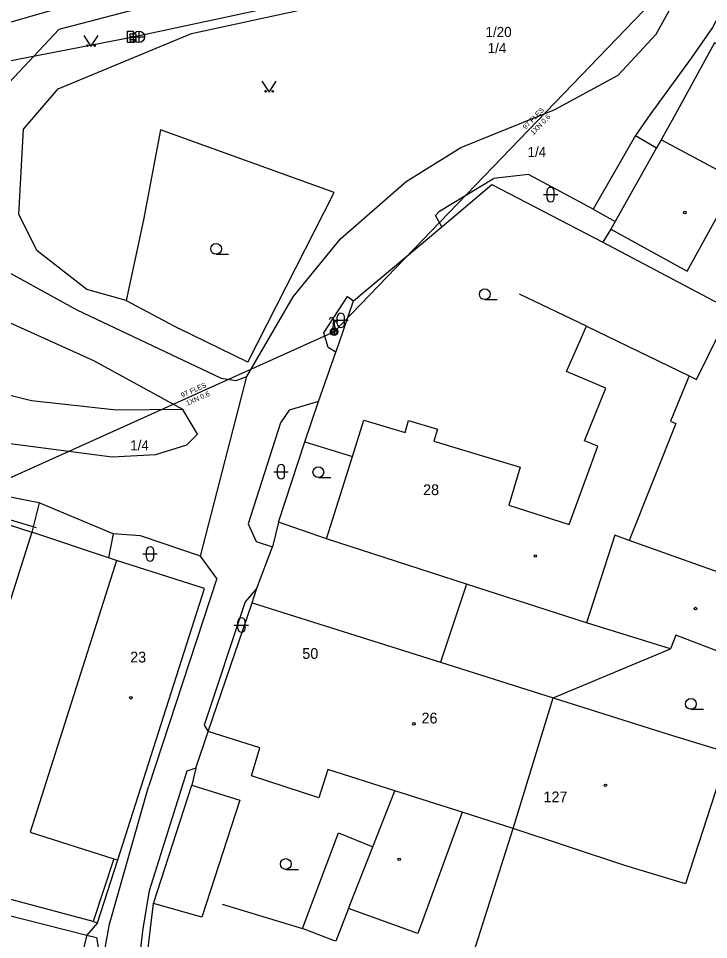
# Model space of a CAD drawing. Extents: x -836739 to -834468, y -1071001 to -1070126.
# Drawn here: x -836549.1 to -836501, y -1070395 to -1070330.7 of the extents above; entities that cross this region are included whole.
import ezdxf

# ---------------------------------------------------------------- set-up
doc = ezdxf.new("R2010")
doc.units = 0
for name, color, linetype in [('f001_pol_linie', 7, 'Continuous'), ('f001_pol_texty', 7, 'Continuous'), ('f001_pol_znacky', 7, 'Continuous'), ('f002_inz_linie_mimo_CETIN', 7, 'Continuous'), ('f005_nadz_ved_linie', 7, 'Continuous'), ('f005_nadz_ved_texty', 7, 'Continuous'), ('f005_nadz_ved_znacky', 7, 'Continuous'), ('f307_kabel_metal', 7, 'Continuous'), ('f307_kabel_metal_ann', 7, 'Continuous'), ('f309_trubka', 7, 'Continuous'), ('f373_podpera', 7, 'Continuous')]:
    doc.layers.add(name, color=color, linetype=linetype)

msp = doc.modelspace()

# ---------------------------------------------------------------- linework, layer by layer
at = {"layer": 'f001_pol_linie'}
for points in [[(-836536.4, -1070368.21), (-836533.17, -1070355.68), (-836529.95, -1070350.14), (-836526.64, -1070346.09), (-836522.06, -1070342.08), (-836518.27, -1070339.72), (-836511.7, -1070337.08), (-836507.28, -1070334.68), (-836504.64, -1070331.81), (-836503.25, -1070329.28), (-836502.09, -1070325.77), (-836501.89, -1070323.62), (-836502.72, -1070321.42), (-836505.15, -1070318.12), (-836506.77, -1070316.06), (-836508.98, -1070315.34)], [(-836541.58, -1070350.39), (-836544.34, -1070349.63), (-836547.79, -1070346.93), (-836549.07, -1070344.38), (-836548.75, -1070338.43), (-836546.32, -1070335.63), (-836537.04, -1070331.76), (-836528.76, -1070329.97), (-836518.57, -1070326.72), (-836515.72, -1070324.62), (-836506.05, -1070328.35), (-836503.77, -1070324.55), (-836503.82, -1070321.79), (-836505.15, -1070318.12)], [(-836503.77, -1070324.55), (-836515, -1070322.63), (-836520.35, -1070325.26), (-836523.26, -1070325.47), (-836531.42, -1070327.59), (-836546.27, -1070331.48), (-836550.47, -1070335.93), (-836551.89, -1070339.77), (-836552.03, -1070343.83), (-836551.31, -1070347.61)], [(-836456.49, -1070361.78), (-836456.25, -1070359.46), (-836459.92, -1070355.96), (-836465.33, -1070351.01), (-836472.65, -1070344.35), (-836480.74, -1070337.07), (-836490.99, -1070328.59), (-836496.17, -1070324.43), (-836496.72, -1070324.41), (-836497.13, -1070324.67), (-836498.53, -1070327.13), (-836499.22, -1070328.53), (-836500.71, -1070331.34), (-836502.21, -1070333.5), (-836505.09, -1070337.45), (-836506.09, -1070338.88), (-836509.04, -1070344.01), (-836513.54, -1070341.59), (-836515.98, -1070341.87)], [(-836561.92, -1070332.6), (-836562.29, -1070333.46), (-836559.69, -1070338.29), (-836553.98, -1070345.27), (-836551.31, -1070347.61), (-836545.02, -1070351.03), (-836534.96, -1070355.81), (-836533.92, -1070355.97), (-836533.17, -1070355.68)], [(-836493.1, -1070336.59), (-836496.65, -1070334.47), (-836500.57, -1070332.42), (-836503.41, -1070337.61)], [(-836615.19, -1070379.26), (-836605.62, -1070372.23), (-836598.73, -1070367.69), (-836589.69, -1070363.97), (-836577.99, -1070361.29), (-836567.54, -1070359.78), (-836561.76, -1070359.47), (-836555.57, -1070359.6), (-836542.56, -1070361.3), (-836539.53, -1070361.13), (-836537.36, -1070360.46), (-836536.61, -1070359.71), (-836537.63, -1070358), (-836543.83, -1070354.6), (-836550.65, -1070351.53), (-836553.41, -1070349.94), (-836556.85, -1070346.77), (-836557.71, -1070345.9), (-836560.14, -1070342.4), (-836564.87, -1070335.97), (-836569.41, -1070333.94)], [(-836502.34, -1070355.64), (-836501.82, -1070355.9), (-836499.44, -1070351.03), (-836494.05, -1070339.35), (-836493.01, -1070337.1)], [(-836503.41, -1070337.61), (-836504.3, -1070339.18)], [(-836533.11, -1070354.69), (-836527.08, -1070342.86), (-836539.2, -1070338.48), (-836540.39, -1070344.76), (-836541.58, -1070350.39), (-836537.92, -1070352.34)], [(-836506.09, -1070338.88), (-836504.62, -1070339.74)], [(-836504.3, -1070339.18), (-836504.62, -1070339.74), (-836507.5, -1070344.87), (-836507.81, -1070345.41)], [(-836502.49, -1070348.34), (-836498.99, -1070342.03), (-836504.3, -1070339.18)], [(-836519.59, -1070345.25), (-836520.02, -1070344.47), (-836519.75, -1070344.15), (-836515.98, -1070341.87)], [(-836525.73, -1070350.4), (-836519.59, -1070345.25), (-836516.09, -1070342.31), (-836508.36, -1070346.32)], [(-836509.04, -1070344.01), (-836507.5, -1070344.87)], [(-836507.81, -1070345.41), (-836508.36, -1070346.32)], [(-836507.81, -1070345.41), (-836502.49, -1070348.34)], [(-836508.36, -1070346.32), (-836499.44, -1070351.03)], [(-836509.51, -1070352.17), (-836514.16, -1070349.95)], [(-836526.98, -1070354), (-836527.51, -1070353.66), (-836527.82, -1070352.64), (-836526.76, -1070351.04), (-836526.15, -1070350.11), (-836525.73, -1070350.4)], [(-836526.79, -1070353.47), (-836525.73, -1070350.4)], [(-836533.11, -1070354.69), (-836537.92, -1070352.34)], [(-836506.52, -1070367.12), (-836507.53, -1070366.76), (-836509.49, -1070372.86), (-836517.87, -1070370.16), (-836527.63, -1070367.01), (-836525.81, -1070361.26), (-836525.01, -1070358.74), (-836522.15, -1070359.6), (-836521.9, -1070358.76), (-836519.88, -1070359.35), (-836520.14, -1070360.2), (-836514.12, -1070362.01), (-836514.92, -1070364.66), (-836510.71, -1070366), (-836508.7, -1070360.55), (-836509.64, -1070360.18), (-836508.16, -1070356.49), (-836510.89, -1070355.34), (-836509.51, -1070352.17), (-836502.34, -1070355.64), (-836503.65, -1070358.81), (-836503.28, -1070358.96), (-836506.52, -1070367.12)], [(-836528.18, -1070357.44), (-836526.98, -1070354), (-836526.79, -1070353.47)], [(-836537.63, -1070358), (-836542.27, -1070358.03), (-836548.18, -1070357.38), (-836559.01, -1070354.67), (-836562.23, -1070356.44)], [(-836528.18, -1070357.44), (-836530.22, -1070358.03), (-836530.82, -1070358.93), (-836533.08, -1070365.97), (-836532.53, -1070367.2), (-836531.39, -1070367.56)], [(-836530.96, -1070365.85), (-836529.13, -1070360.25), (-836528.18, -1070357.44)], [(-836529.13, -1070360.25), (-836525.81, -1070361.26)], [(-836547.65, -1070364.49), (-836556.3, -1070362.82), (-836560.36, -1070362.88), (-836566.97, -1070363.32), (-836574.87, -1070363.96), (-836583.1, -1070365.51), (-836589.57, -1070367.22), (-836595.04, -1070369.19), (-836598.97, -1070371.82)], [(-836548.17, -1070366.54), (-836554, -1070384.9), (-836561.97, -1070382.37), (-836556.16, -1070364.42), (-836556.02, -1070364), (-836548.17, -1070366.54)], [(-836547.65, -1070364.49), (-836548.17, -1070366.54)], [(-836542.49, -1070366.67), (-836547.65, -1070364.49)], [(-836527.63, -1070367.01), (-836530.96, -1070365.85), (-836531.39, -1070367.56)], [(-836542.26, -1070368.53), (-836542.82, -1070368.34), (-836548.17, -1070366.54)], [(-836542.49, -1070366.67), (-836542.82, -1070368.34)], [(-836535.27, -1070369.78), (-836536.4, -1070368.21), (-836540.58, -1070366.8), (-836542.49, -1070366.67)], [(-836491.71, -1070372.41), (-836506.52, -1070367.12)], [(-836532.48, -1070370.45), (-836531.39, -1070367.56)], [(-836542.44, -1070389.32), (-836542.18, -1070389.4), (-836536.13, -1070370.46), (-836542.26, -1070368.53), (-836542.37, -1070368.88), (-836548.27, -1070387.46), (-836542.44, -1070389.32)], [(-836535.27, -1070369.78), (-836540.03, -1070384.3)], [(-836532.48, -1070370.45), (-836533.3, -1070371.41), (-836536.15, -1070380), (-836535.86, -1070380.44)], [(-836532.8, -1070371.47), (-836532.48, -1070370.45)], [(-836517.87, -1070370.16), (-836519.68, -1070375.61)], [(-836514.6, -1070387.21), (-836518.17, -1070386.07), (-836522.86, -1070384.58), (-836527.53, -1070383.09), (-836528.16, -1070385.07), (-836532.84, -1070383.54), (-836532.27, -1070381.59), (-836535.86, -1070380.44), (-836532.8, -1070371.47), (-836519.68, -1070375.61), (-836511.83, -1070378.09)], [(-836503.28, -1070373.72), (-836503.65, -1070374.67), (-836509.49, -1070372.86)], [(-836499.82, -1070375.05), (-836503.28, -1070373.72)], [(-836511.83, -1070378.09), (-836503.65, -1070374.67)], [(-836514.6, -1070387.21), (-836511.83, -1070378.09)], [(-836511.83, -1070378.09), (-836503.8, -1070380.64)], [(-836536.74, -1070383), (-836535.86, -1070380.44)], [(-836503.8, -1070380.64), (-836499.62, -1070381.9)], [(-836499.62, -1070381.9), (-836502.6, -1070391.06)], [(-836536.74, -1070383), (-836537.35, -1070383.22), (-836539.98, -1070391.55), (-836540.43, -1070394.17), (-836540.74, -1070396.93), (-836539.94, -1070401), (-836536.26, -1070408.95), (-836531.81, -1070417.56), (-836531.19, -1070418.64), (-836530.26, -1070420.61), (-836527.07, -1070426.97), (-836526.57, -1070426.77)], [(-836536.74, -1070383), (-836537.02, -1070384.18)], [(-836531.1, -1070469.82), (-836529.4, -1070467.3), (-836528.17, -1070465.13), (-836524.83, -1070452.23), (-836524.15, -1070447.92), (-836523.94, -1070446.04), (-836523.89, -1070443.38), (-836524.1, -1070441.71), (-836524.87, -1070438.13), (-836528.78, -1070429.39), (-836535.78, -1070414.25), (-836542.47, -1070401.26), (-836543.02, -1070395.42), (-836542.75, -1070393.88), (-836540.03, -1070384.3)], [(-836536.32, -1070393.39), (-836539.69, -1070392.43), (-836537.02, -1070384.18), (-836533.66, -1070385.23), (-836536.32, -1070393.39)], [(-836518.17, -1070386.07), (-836521.26, -1070394.54), (-836526.09, -1070392.78), (-836524.39, -1070388.48), (-836522.86, -1070384.58)], [(-836543.88, -1070393.69), (-836556.34, -1070390.37), (-836565.29, -1070387.3), (-836567.72, -1070386.62)], [(-836517.87, -1070397.43), (-836514.6, -1070387.21)], [(-836506.82, -1070389.78), (-836514.6, -1070387.21)], [(-836526.09, -1070392.78), (-836526.98, -1070395.07), (-836527.25, -1070394.97), (-836529.3, -1070394.19), (-836526.78, -1070387.52), (-836524.39, -1070388.48)], [(-836542.44, -1070389.32), (-836543.88, -1070393.69), (-836543.58, -1070393.79), (-836542.18, -1070389.4)], [(-836502.6, -1070391.06), (-836506.82, -1070389.78)], [(-836547.67, -1070408.02), (-836561.18, -1070404.66), (-836558.85, -1070395.08), (-836554.33, -1070396.22), (-836554.25, -1070395.86), (-836553.6, -1070393.14), (-836553.41, -1070392.35), (-836544.32, -1070394.64), (-836547.67, -1070408.02)], [(-836533.93, -1070412.16), (-836539.42, -1070400.74), (-836540.18, -1070396.5), (-836539.69, -1070392.43)], [(-836534.9, -1070392.48), (-836529.3, -1070394.19)], [(-836543.58, -1070393.79), (-836544.32, -1070394.64)], [(-836544.32, -1070394.64), (-836543.66, -1070394.81), (-836543.54, -1070395.48), (-836542.9, -1070401.49), (-836541.59, -1070404), (-836536.99, -1070412.69)]]:
    msp.add_lwpolyline(points, dxfattribs=at)
at = {"layer": 'f001_pol_znacky'}
for p, q in [((-836512.25, -1070343.25), (-836512.25, -1070342.75)), ((-836511.75, -1070343.25), (-836511.75, -1070342.75)), ((-836512.5, -1070343), (-836511.5, -1070343)), ((-836535.32, -1070347.165), (-836534.445, -1070347.165)), ((-836516.59, -1070350.325), (-836515.715, -1070350.325)), ((-836527.12, -1070351.77), (-836526.12, -1070351.77)), ((-836526.87, -1070352.02), (-836526.87, -1070351.52)), ((-836526.37, -1070352.02), (-836526.37, -1070351.52)), ((-836531.04, -1070362.58), (-836531.04, -1070362.08)), ((-836530.54, -1070362.58), (-836530.54, -1070362.08)), ((-836531.29, -1070362.33), (-836530.29, -1070362.33)), ((-836528.19, -1070362.735), (-836527.315, -1070362.735)), ((-836540.17, -1070368.31), (-836540.17, -1070367.81)), ((-836539.67, -1070368.31), (-836539.67, -1070367.81)), ((-836540.42, -1070368.06), (-836539.42, -1070368.06)), ((-836534.05, -1070373.02), (-836533.05, -1070373.02)), ((-836533.8, -1070373.27), (-836533.8, -1070372.77)), ((-836533.3, -1070373.27), (-836533.3, -1070372.77)), ((-836502.22, -1070378.895), (-836501.345, -1070378.895)), ((-836530.46, -1070390.055), (-836529.585, -1070390.055))]:
    msp.add_line(p, q, dxfattribs=at)
for points in [[(-836544.54, -1070331.92), (-836544.04, -1070332.67), (-836543.54, -1070331.92)], [(-836532.12, -1070335.1), (-836531.62, -1070335.85), (-836531.12, -1070335.1)]]:
    msp.add_lwpolyline(points, dxfattribs=at)
for centre, radius in [((-836544.29, -1070332.62), 0.05), ((-836543.79, -1070332.62), 0.05), ((-836531.87, -1070335.8), 0.05), ((-836531.37, -1070335.8), 0.05), ((-836502.65, -1070344.25), 0.0875), ((-836535.32, -1070346.79), 0.375), ((-836516.59, -1070349.95), 0.375), ((-836527.09, -1070352.57), 0.25), ((-836528.19, -1070362.36), 0.375), ((-836513.07, -1070368.21), 0.0875), ((-836501.9, -1070371.87), 0.0875), ((-836541.26, -1070378.09), 0.0875), ((-836502.22, -1070378.52), 0.375), ((-836521.53, -1070379.91), 0.0875), ((-836508.18, -1070384.2), 0.0875), ((-836530.46, -1070389.68), 0.375), ((-836522.56, -1070389.36), 0.0875)]:
    msp.add_circle(centre, radius, dxfattribs=at)
for centre, start, end in [((-836512, -1070342.75), 0, 179.99999), ((-836512, -1070343.25), 179.99999, 359.99999), ((-836526.62, -1070351.52), 0, 179.99999), ((-836526.62, -1070352.02), 179.99999, 359.99999), ((-836530.79, -1070362.08), 0, 179.99999), ((-836530.79, -1070362.58), 179.99999, 359.99999), ((-836539.92, -1070367.81), 0, 179.99999), ((-836539.92, -1070368.31), 179.99999, 359.99999), ((-836533.55, -1070372.77), 0, 179.99999), ((-836533.55, -1070373.27), 179.99999, 359.99999)]:
    msp.add_arc(centre, 0.25, start, end, dxfattribs=at)
at = {"layer": 'f002_inz_linie_mimo_CETIN'}
msp.add_lwpolyline([(-836547.83, -1070366.24), (-836557.43, -1070363.37)], dxfattribs=at)
at = {"layer": 'f005_nadz_ved_linie'}
for points in [[(-836583.936, -1070340.301), (-836541.108, -1070332.001), (-836507.2, -1070324.72)], [(-836507.2, -1070324.72), (-836505.56, -1070330.22), (-836527.09, -1070352.57), (-836554.12, -1070364.76)]]:
    msp.add_lwpolyline(points, dxfattribs=at)
at = {"layer": 'f005_nadz_ved_znacky'}
for p, q in [((-836540.708, -1070331.601), (-836540.708, -1070332.401)), ((-836541.108, -1070332.001), (-836540.308, -1070332.001))]:
    msp.add_line(p, q, dxfattribs=at)
msp.add_lwpolyline([(-836541.501, -1070331.597), (-836541.108, -1070331.597), (-836541.108, -1070332.404), (-836541.501, -1070332.404)], close=True, dxfattribs=at)
msp.add_circle((-836540.708, -1070332.001), 0.4, dxfattribs=at)
at = {"layer": 'f307_kabel_metal'}
for points in [[(-836583.936, -1070340.301), (-836541.108, -1070332.001), (-836507.2, -1070324.72)], [(-836507.2, -1070324.72), (-836505.56, -1070330.22), (-836527.09, -1070352.57), (-836554.12, -1070364.76)]]:
    msp.add_lwpolyline(points, dxfattribs=at)
at = {"layer": 'f309_trubka'}
msp.add_lwpolyline([(-836601.098, -1070348.885), (-836590.874, -1070341.686), (-836579.049, -1070338.909), (-836578.319, -1070338.737), (-836573.24, -1070337.643), (-836568.734, -1070336.652), (-836561.043, -1070334.862), (-836549.834, -1070331.035), (-836542.483, -1070328.89), (-836541.763, -1070328.68), (-836539.329, -1070327.97), (-836531.65, -1070325.714), (-836521.049, -1070321.997), (-836514.568, -1070319.658), (-836505.529, -1070314.952), (-836501.069, -1070312.194)], dxfattribs=at)
at = {"layer": 'f373_podpera'}
for p, q in [((-836540.908, -1070332.201), (-836541.308, -1070332.201)), ((-836541.108, -1070332.001), (-836541.108, -1070332.401)), ((-836527.131, -1070351.727), (-836527.172, -1070352.318)), ((-836527.131, -1070351.727), (-836527.033, -1070352.311)), ((-836527.1, -1070352.37), (-836527.08, -1070352.77)), ((-836527.29, -1070352.58), (-836526.89, -1070352.56))]:
    msp.add_line(p, q, dxfattribs=at)
msp.add_lwpolyline([(-836540.906, -1070331.804), (-836540.906, -1070332.001), (-836541.31, -1070332.001), (-836541.31, -1070331.804)], close=True, dxfattribs=at)
for centre, radius in [((-836541.108, -1070332.201), 0.2), ((-836527.09, -1070352.57), 0.265), ((-836527.09, -1070352.57), 0.2)]:
    msp.add_circle(centre, radius, dxfattribs=at)
for centre, start, end in [((-836527.28, -1070351.734), 2.81, 182.80999), ((-836526.983, -1070351.719), 182.81001, 2.81)]:
    msp.add_arc(centre, 0.148, start, end, dxfattribs=at)

# ---------------------------------------------------------------- texts
at = {"layer": 'f001_pol_texty'}
for s, p in [('28', (-836520.89, -1070363.96)), ('23', (-836541.31, -1070375.63)), ('50', (-836529.31, -1070375.38)), ('26', (-836521, -1070379.88)), ('127', (-836512.5, -1070385.38))]:
    msp.add_text(s, height=0.75, dxfattribs=at).set_placement(p)
at = {"layer": 'f005_nadz_ved_texty'}
for s, p in [('1/20', (-836516.54, -1070332.01)), ('1/4', (-836516.39, -1070333.14)), ('1/4', (-836513.61, -1070340.38)), ('1/4', (-836541.31, -1070360.84))]:
    msp.add_text(s, height=0.7, dxfattribs=at).set_placement(p)
at = {"layer": 'f307_kabel_metal_ann'}
for s, rotation, p in [('97 FLES', 46.07, (-836513.736, -1070338.491)), (' 1XN 0,6', 46.07, (-836513.288, -1070338.963)), ('97 FLES', 24.27, (-836537.677, -1070357.18)), (' 1XN 0,6', 24.27, (-836537.436, -1070357.784))]:
    msp.add_text(s, height=0.35, rotation=rotation, dxfattribs=at).set_placement(p)

doc.saveas('drawing.dxf')
